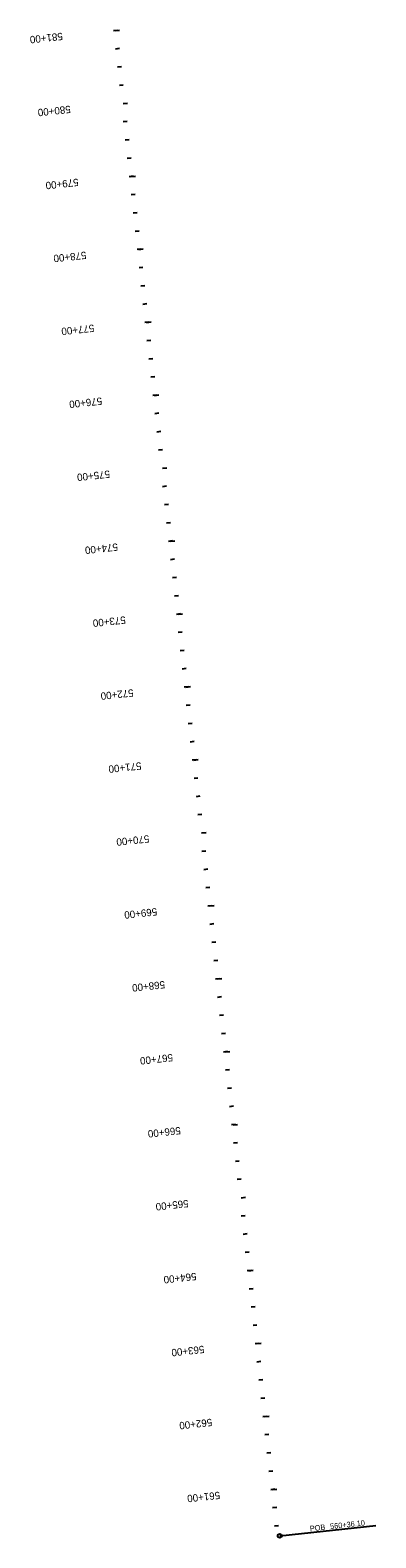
# Model space of a CAD drawing. Extents: x 16453950 to 16454580, y 7022804 to 7039381.
# Drawn here: x 16454097 to 16454569, y 7022804 to 7024859 of the extents above; entities that cross this region are included whole.
import ezdxf

# ---------------------------------------------------------------- set-up
doc = ezdxf.new("R2010")
doc.units = 0
for name, color, linetype in [('TextAlignment', 7, 'Continuous'), ('TextAlignmentLrg', 7, 'Continuous'), ('TextAlignmentSml', 7, 'Continuous')]:
    doc.layers.add(name, color=color, linetype=linetype)

msp = doc.modelspace()

# ---------------------------------------------------------------- linework, layer by layer
at = {"layer": 'TextAlignment'}
for p in [(16454437.9, 7022806.7), (16454569.2, 7022820.8)]:
    msp.add_line(p, (16454569.2, 7022820.8), dxfattribs=at)
msp.add_circle((16454437.9, 7022806.7), 2.67, dxfattribs=at)
at = {"layer": 'TextAlignmentLrg'}
for p, q in [((16454216.4, 7024858.6), (16454211, 7024858.1)), ((16454224.1, 7024758.9), (16454230.2, 7024759.5)), ((16454237.9, 7024659.8), (16454232.5, 7024659.2)), ((16454248.6, 7024560.4), (16454243.2, 7024559.8)), ((16454259.4, 7024461), (16454253.9, 7024460.4)), ((16454270.1, 7024361.5), (16454264.7, 7024360.9)), ((16454277.8, 7024261.8), (16454283.9, 7024262.4)), ((16454291.6, 7024162.7), (16454286.1, 7024162.1)), ((16454302.3, 7024063.3), (16454296.9, 7024062.7)), ((16454313, 7023963.8), (16454307.6, 7023963.3)), ((16454323.8, 7023864.4), (16454318.3, 7023863.8)), ((16454331.4, 7023764.7), (16454337.5, 7023765.3)), ((16454345.2, 7023665.6), (16454339.8, 7023665)), ((16454356, 7023566.1), (16454350.5, 7023565.6)), ((16454366.7, 7023466.7), (16454361.3, 7023466.1)), ((16454377.4, 7023367.3), (16454372, 7023366.7)), ((16454385.1, 7023267.6), (16454391.2, 7023268.2)), ((16454398.9, 7023168.5), (16454393.5, 7023167.9)), ((16454409.6, 7023069), (16454404.2, 7023068.5)), ((16454420.3, 7022969.6), (16454414.9, 7022969)), ((16454431.1, 7022870.2), (16454425.6, 7022869.6))]:
    msp.add_line(p, q, dxfattribs=at)
at = {"layer": 'TextAlignmentSml'}
for p, q in [((16454213.4, 7024858.3), (16454219.5, 7024859)), ((16454219.1, 7024833.8), (16454213.7, 7024833.2)), ((16454221.8, 7024808.9), (16454216.4, 7024808.3)), ((16454224.5, 7024784.1), (16454219.1, 7024783.5)), ((16454224.1, 7024758.9), (16454230.2, 7024759.5)), ((16454229.8, 7024734.4), (16454224.4, 7024733.8)), ((16454232.5, 7024709.5), (16454227.1, 7024708.9)), ((16454235.2, 7024684.7), (16454229.8, 7024684.1)), ((16454234.9, 7024659.5), (16454240.9, 7024660.1)), ((16454240.6, 7024634.9), (16454235.2, 7024634.4)), ((16454243.3, 7024610.1), (16454237.8, 7024609.5)), ((16454245.9, 7024585.2), (16454240.5, 7024584.6)), ((16454245.6, 7024560), (16454251.7, 7024560.7)), ((16454251.3, 7024535.5), (16454245.9, 7024534.9)), ((16454254, 7024510.7), (16454248.6, 7024510.1)), ((16454256.7, 7024485.8), (16454251.2, 7024485.2)), ((16454256.3, 7024460.6), (16454262.4, 7024461.3)), ((16454262, 7024436.1), (16454256.6, 7024435.5)), ((16454264.7, 7024411.2), (16454259.3, 7024410.7)), ((16454267.4, 7024386.4), (16454262, 7024385.8)), ((16454267, 7024361.2), (16454273.1, 7024361.9)), ((16454272.8, 7024336.7), (16454267.3, 7024336.1)), ((16454275.5, 7024311.8), (16454270, 7024311.2)), ((16454278.1, 7024287), (16454272.7, 7024286.4)), ((16454277.8, 7024261.8), (16454283.9, 7024262.4)), ((16454283.5, 7024237.3), (16454278.1, 7024236.7)), ((16454286.2, 7024212.4), (16454280.8, 7024211.8)), ((16454288.9, 7024187.5), (16454283.4, 7024187)), ((16454288.5, 7024162.4), (16454294.6, 7024163)), ((16454294.2, 7024137.8), (16454288.8, 7024137.2)), ((16454296.9, 7024113), (16454291.5, 7024112.4)), ((16454299.6, 7024088.1), (16454294.2, 7024087.5)), ((16454299.2, 7024062.9), (16454305.3, 7024063.6)), ((16454305, 7024038.4), (16454299.5, 7024037.8)), ((16454307.7, 7024013.6), (16454302.2, 7024013)), ((16454310.3, 7023988.7), (16454304.9, 7023988.1)), ((16454310, 7023963.5), (16454316.1, 7023964.2)), ((16454315.7, 7023939), (16454310.3, 7023938.4)), ((16454318.4, 7023914.1), (16454313, 7023913.5)), ((16454321.1, 7023889.3), (16454315.6, 7023888.7)), ((16454320.7, 7023864.1), (16454326.8, 7023864.7)), ((16454326.4, 7023839.6), (16454321, 7023839)), ((16454329.1, 7023814.7), (16454323.7, 7023814.1)), ((16454331.8, 7023789.9), (16454326.4, 7023789.3)), ((16454331.4, 7023764.7), (16454337.5, 7023765.3)), ((16454337.2, 7023740.1), (16454331.7, 7023739.6)), ((16454339.9, 7023715.3), (16454334.4, 7023714.7)), ((16454342.5, 7023690.4), (16454337.1, 7023689.8)), ((16454342.2, 7023665.2), (16454348.3, 7023665.9)), ((16454347.9, 7023640.7), (16454342.5, 7023640.1)), ((16454350.6, 7023615.9), (16454345.2, 7023615.3)), ((16454353.3, 7023591), (16454347.8, 7023590.4)), ((16454352.9, 7023565.8), (16454359, 7023566.5)), ((16454358.6, 7023541.3), (16454353.2, 7023540.7)), ((16454361.3, 7023516.4), (16454355.9, 7023515.9)), ((16454364, 7023491.6), (16454358.6, 7023491)), ((16454363.6, 7023466.4), (16454369.7, 7023467.1)), ((16454369.4, 7023441.9), (16454363.9, 7023441.3)), ((16454372, 7023417), (16454366.6, 7023416.4)), ((16454374.7, 7023392.2), (16454369.3, 7023391.6)), ((16454374.4, 7023367), (16454380.5, 7023367.6)), ((16454380.1, 7023342.4), (16454374.7, 7023341.9)), ((16454382.8, 7023317.6), (16454377.4, 7023317)), ((16454385.5, 7023292.7), (16454380, 7023292.2)), ((16454385.1, 7023267.6), (16454391.2, 7023268.2)), ((16454390.8, 7023243), (16454385.4, 7023242.4)), ((16454393.5, 7023218.2), (16454388.1, 7023217.6)), ((16454396.2, 7023193.3), (16454390.8, 7023192.7)), ((16454395.8, 7023168.1), (16454401.9, 7023168.8)), ((16454401.6, 7023143.6), (16454396.1, 7023143)), ((16454404.2, 7023118.7), (16454398.8, 7023118.2)), ((16454406.9, 7023093.9), (16454401.5, 7023093.3)), ((16454406.6, 7023068.7), (16454412.7, 7023069.4)), ((16454412.3, 7023044.2), (16454406.9, 7023043.6)), ((16454415, 7023019.3), (16454409.5, 7023018.7)), ((16454417.7, 7022994.5), (16454412.2, 7022993.9)), ((16454417.3, 7022969.3), (16454423.4, 7022969.9)), ((16454423, 7022944.8), (16454417.6, 7022944.2)), ((16454425.7, 7022919.9), (16454420.3, 7022919.3)), ((16454428.4, 7022895), (16454423, 7022894.5)), ((16454428, 7022869.9), (16454434.1, 7022870.5)), ((16454433.8, 7022845.3), (16454428.3, 7022844.8)), ((16454436.4, 7022820.5), (16454431, 7022819.9))]:
    msp.add_line(p, q, dxfattribs=at)

# ---------------------------------------------------------------- texts
at = {"layer": 'TextAlignment'}
for s, p in [('560+36.10', (16454507.1, 7022815.8)), ('POB ', (16454479.5, 7022812.8))]:
    msp.add_text(s, height=7.5, rotation=6.161, dxfattribs=at).set_placement(p)
at = {"layer": 'TextAlignmentLrg'}
for s, p in [('580+00', (16454152.1, 7024756.2)), ('575+00', (16454205.7, 7024259)), ('570+00', (16454259.4, 7023761.9)), ('565+00', (16454313, 7023264.8))]:
    msp.add_text(s, height=10.02, rotation=186.161, dxfattribs=at).set_placement(p)
at = {"layer": 'TextAlignmentSml'}
for s, p in [('581+00', (16454141.3, 7024855.6)), ('580+00', (16454152.1, 7024756.2)), ('579+00', (16454162.8, 7024656.7)), ('578+00', (16454173.5, 7024557.3)), ('577+00', (16454184.3, 7024457.9)), ('576+00', (16454195, 7024358.5)), ('575+00', (16454205.7, 7024259)), ('574+00', (16454216.5, 7024159.6)), ('573+00', (16454227.2, 7024060.2)), ('572+00', (16454237.9, 7023960.8)), ('571+00', (16454248.6, 7023861.3)), ('570+00', (16454259.4, 7023761.9)), ('569+00', (16454270.1, 7023662.5)), ('568+00', (16454280.8, 7023563.1)), ('567+00', (16454291.6, 7023463.7)), ('566+00', (16454302.3, 7023364.2)), ('565+00', (16454313, 7023264.8)), ('564+00', (16454323.8, 7023165.4)), ('563+00', (16454334.5, 7023066)), ('562+00', (16454345.2, 7022966.5)), ('561+00', (16454356, 7022867.1))]:
    msp.add_text(s, height=10.02, rotation=186.161, dxfattribs=at).set_placement(p)

doc.saveas('drawing.dxf')
